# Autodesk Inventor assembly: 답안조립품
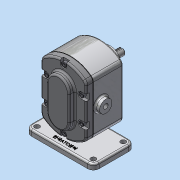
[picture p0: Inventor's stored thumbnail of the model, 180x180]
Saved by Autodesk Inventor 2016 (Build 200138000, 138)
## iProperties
Created: 2019-03
Part Number: 답안조립품
Document SubType Name: Assembly
Designer: Administrator
Author: Administrator
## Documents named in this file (11)
- C:\Users\Administrator\Desktop\490307V1005\답안조립품.iam
- C:\Users\Administrator\Desktop\490307V1005\본체.ipt
- C:\Users\Administrator\Desktop\490307V1005\메인축.ipt
- C:\Users\Administrator\Desktop\490307V1005\오일 실 16 28 7.ipt
- C:\Users\Administrator\Desktop\490307V1005\베어링부시.ipt
- C:\Users\Administrator\Desktop\490307V1005\키 6 x 6 x 18.ipt
- C:\Users\Administrator\Desktop\490307V1005\스퍼기어.ipt
- C:\Users\Administrator\Desktop\490307V1005\서브축.ipt
- C:\Users\Administrator\Desktop\490307V1005\볼트 M5.ipt
- C:\Users\Administrator\Desktop\490307V1005\커버.ipt
- C:\Users\Administrator\Desktop\490307V1005\개스킷.ipt
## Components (1 placed, 1 different names)
1. 개스킷:1
